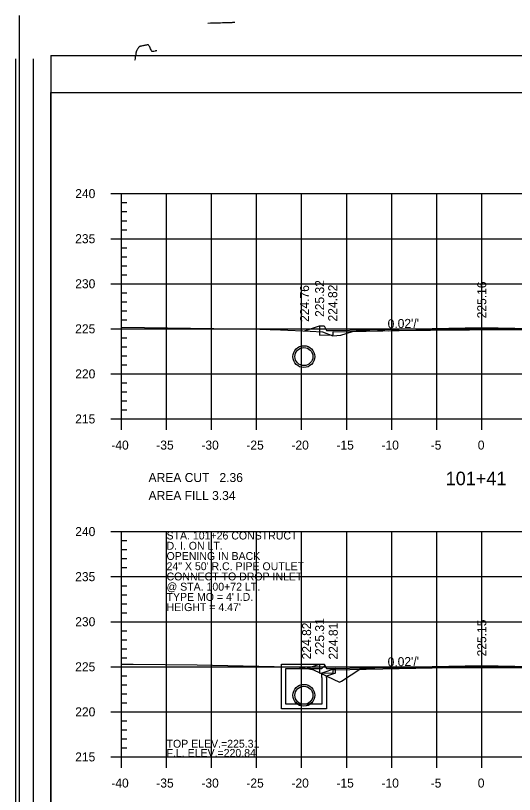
# Model space of a CAD drawing. Extents: x 1367903 to 1373764, y 376865 to 382130.
# Drawn here: x 1369737.8 to 1369848.6, y 377447.5 to 377620.4 of the extents above; entities that cross this region are included whole.
import ezdxf

# ---------------------------------------------------------------- set-up
doc = ezdxf.new("R2010")
doc.units = 0
for name, color, linetype in [('R_Axis', 7, 'Continuous'), ('R_Axis Annot', 7, 'Continuous'), ('R_Border', 7, 'Continuous'), ('R_Border PE', 7, 'Continuous'), ('R_Draft', 7, 'Continuous'), ('R_Exist Surface', 7, 'Continuous'), ('R_Fin Surface', 7, 'Continuous'), ('R_Fin Surface Annot', 7, 'Continuous'), ('R_Grid', 7, 'Continuous'), ('R_Water', 7, 'Continuous'), ('R_Water Annot', 7, 'Continuous')]:
    doc.layers.add(name, color=color, linetype=linetype)

msp = doc.modelspace()

# ---------------------------------------------------------------- linework, layer by layer
for p, q in [((1369796.84, 377476.45), (1369806.34, 377476.45)), ((1369796.84, 377473.45), (1369796.84, 377476.45)), ((1369797.84, 377473.45), (1369797.84, 377475.45)), ((1369797.84, 377475.45), (1369805.84, 377475.45)), ((1369806.5, 377476.12), (1369805.84, 377475.45)), ((1369808.84, 377475.49), (1369805.84, 377474.45)), ((1369806.5, 377476.12), (1369806.34, 377476.45)), ((1369805.84, 377473.45), (1369805.84, 377474.45)), ((1369808.84, 377474.43), (1369806.84, 377473.74)), ((1369806.84, 377473.45), (1369806.84, 377473.74))]:
    msp.add_line(p, q)
for points in [[(1369805.34, 377551.47), (1369805.34, 377550.81), (1369805.34, 377550.81), (1369805.34, 377549.44), (1369808.34, 377549.5), (1369808.34, 377550.17), (1369841.34, 377550.83), (1369874.34, 377550.17), (1369874.34, 377549.5), (1369877.34, 377549.44), (1369877.34, 377550.89), (1369891.34, 377551.17), (1369891.34, 377551.75)], [(1369805.34, 377476.45), (1369805.34, 377475.78), (1369805.34, 377475.78), (1369805.34, 377474.42), (1369808.34, 377474.48), (1369808.34, 377475.14), (1369841.34, 377475.8), (1369874.34, 377475.14), (1369874.34, 377474.48), (1369877.34, 377474.42), (1369877.34, 377475.86), (1369891.34, 377476.14), (1369891.34, 377476.73)], [(1369808.84, 377474.43), (1369808.84, 377475.49)]]:
    msp.add_lwpolyline(points)
at = {"layer": 'R_Axis'}
for p, q in [((1369758.94, 377580.84), (1369763.74, 377580.84)), ((1369761.34, 377530.84), (1369761.34, 377580.84)), ((1369761.34, 377578.84), (1369762.54, 377578.84)), ((1369761.34, 377576.84), (1369762.54, 377576.84)), ((1369761.34, 377574.84), (1369762.54, 377574.84)), ((1369761.34, 377572.84), (1369762.54, 377572.84)), ((1369758.94, 377570.84), (1369763.74, 377570.84)), ((1369761.34, 377568.84), (1369762.54, 377568.84)), ((1369761.34, 377566.84), (1369762.54, 377566.84)), ((1369761.34, 377564.84), (1369762.54, 377564.84)), ((1369761.34, 377562.84), (1369762.54, 377562.84)), ((1369758.94, 377560.84), (1369763.74, 377560.84)), ((1369761.34, 377558.84), (1369762.54, 377558.84)), ((1369761.34, 377556.84), (1369762.54, 377556.84)), ((1369761.34, 377554.84), (1369762.54, 377554.84)), ((1369761.34, 377552.84), (1369762.54, 377552.84)), ((1369758.94, 377550.84), (1369763.74, 377550.84)), ((1369761.34, 377548.84), (1369762.54, 377548.84)), ((1369761.34, 377546.84), (1369762.54, 377546.84)), ((1369761.34, 377544.84), (1369762.54, 377544.84)), ((1369761.34, 377542.84), (1369762.54, 377542.84)), ((1369758.94, 377540.84), (1369763.74, 377540.84)), ((1369761.34, 377538.84), (1369762.54, 377538.84)), ((1369761.34, 377536.84), (1369762.54, 377536.84)), ((1369761.34, 377534.84), (1369762.54, 377534.84)), ((1369761.34, 377528.44), (1369761.34, 377533.24)), ((1369761.34, 377532.84), (1369762.54, 377532.84)), ((1369771.34, 377528.44), (1369771.34, 377533.24)), ((1369781.34, 377528.44), (1369781.34, 377533.24)), ((1369791.34, 377528.44), (1369791.34, 377533.24)), ((1369801.34, 377528.44), (1369801.34, 377533.24)), ((1369811.34, 377528.44), (1369811.34, 377533.24)), ((1369821.34, 377528.44), (1369821.34, 377533.24)), ((1369831.34, 377528.44), (1369831.34, 377533.24)), ((1369841.34, 377528.44), (1369841.34, 377533.24)), ((1369758.94, 377530.84), (1369763.74, 377530.84)), ((1369761.34, 377530.84), (1369921.34, 377530.84)), ((1369758.94, 377505.84), (1369763.74, 377505.84)), ((1369761.34, 377455.84), (1369761.34, 377505.84)), ((1369761.34, 377503.84), (1369762.54, 377503.84)), ((1369761.34, 377501.84), (1369762.54, 377501.84)), ((1369761.34, 377499.84), (1369762.54, 377499.84)), ((1369761.34, 377497.84), (1369762.54, 377497.84)), ((1369758.94, 377495.84), (1369763.74, 377495.84)), ((1369761.34, 377493.84), (1369762.54, 377493.84)), ((1369761.34, 377491.84), (1369762.54, 377491.84)), ((1369761.34, 377489.84), (1369762.54, 377489.84)), ((1369761.34, 377487.84), (1369762.54, 377487.84)), ((1369758.94, 377485.84), (1369763.74, 377485.84)), ((1369761.34, 377483.84), (1369762.54, 377483.84)), ((1369761.34, 377481.84), (1369762.54, 377481.84)), ((1369761.34, 377479.84), (1369762.54, 377479.84)), ((1369761.34, 377477.84), (1369762.54, 377477.84)), ((1369758.94, 377475.84), (1369763.74, 377475.84)), ((1369761.34, 377473.84), (1369762.54, 377473.84)), ((1369761.34, 377471.84), (1369762.54, 377471.84)), ((1369761.34, 377469.84), (1369762.54, 377469.84)), ((1369761.34, 377467.84), (1369762.54, 377467.84)), ((1369758.94, 377465.84), (1369763.74, 377465.84)), ((1369761.34, 377463.84), (1369762.54, 377463.84)), ((1369761.34, 377461.84), (1369762.54, 377461.84)), ((1369761.34, 377459.84), (1369762.54, 377459.84)), ((1369761.34, 377453.44), (1369761.34, 377458.24)), ((1369771.34, 377453.44), (1369771.34, 377458.24)), ((1369781.34, 377453.44), (1369781.34, 377458.24)), ((1369791.34, 377453.44), (1369791.34, 377458.24)), ((1369801.34, 377453.44), (1369801.34, 377458.24)), ((1369811.34, 377453.44), (1369811.34, 377458.24)), ((1369821.34, 377453.44), (1369821.34, 377458.24)), ((1369831.34, 377453.44), (1369831.34, 377458.24)), ((1369841.34, 377453.44), (1369841.34, 377458.24)), ((1369761.34, 377457.84), (1369762.54, 377457.84)), ((1369758.94, 377455.84), (1369763.74, 377455.84)), ((1369761.34, 377455.84), (1369921.34, 377455.84))]:
    msp.add_line(p, q, dxfattribs=at)
at = {"layer": 'R_Border'}
for p, q in [((1369738.61, 377620.35), (1369738.61, 377279.12)), ((1369745.64, 377611.47), (1369949.96, 377611.47)), ((1369745.64, 377611.47), (1369745.64, 377280.59))]:
    msp.add_line(p, q, dxfattribs=at)
at = {"layer": 'R_Border PE'}
for p, q in [((1369737.81, 377610.76), (1369737.81, 377288.8)), ((1369741.72, 377610.76), (1369741.72, 377288.8)), ((1369745.64, 377603.25), (1369949.96, 377603.25)), ((1369745.64, 377288.8), (1369745.64, 377603.25))]:
    msp.add_line(p, q, dxfattribs=at)
for points in [[(1369786.51, 377618.79), (1369786.17, 377618.78), (1369785.97, 377618.78), (1369785.81, 377618.77), (1369785.58, 377618.76), (1369785.42, 377618.76), (1369785.23, 377618.75), (1369784.98, 377618.75), (1369784.79, 377618.74), (1369784.51, 377618.73), (1369784.41, 377618.73), (1369784.36, 377618.73), (1369784.14, 377618.72), (1369784.03, 377618.72), (1369783.81, 377618.71), (1369783.73, 377618.72), (1369783.31, 377618.7), (1369783.06, 377618.7), (1369782.95, 377618.7)], [(1369782.5, 377618.69), (1369782.44, 377618.69), (1369782.17, 377618.68), (1369782.04, 377618.68), (1369781.97, 377618.67), (1369781.81, 377618.67), (1369781.45, 377618.66), (1369781.12, 377618.65), (1369780.49, 377618.63)], [(1369782.95, 377618.7), (1369782.5, 377618.69)], [(1369769.2, 377612.54), (1369769.18, 377612.55), (1369769.16, 377612.55), (1369769.14, 377612.55), (1369769.12, 377612.55), (1369769.09, 377612.55), (1369769.06, 377612.55), (1369769.04, 377612.55), (1369768.9, 377612.51), (1369768.78, 377612.48), (1369768.51, 377612.41), (1369768.29, 377612.36), (1369768.27, 377612.35), (1369768.25, 377612.35), (1369768.22, 377612.34), (1369768.21, 377612.34), (1369768.2, 377612.35), (1369768.18, 377612.35), (1369768.16, 377612.36), (1369768.13, 377612.38), (1369768.11, 377612.39), (1369768.09, 377612.4), (1369768.08, 377612.42), (1369768.06, 377612.45), (1369768.05, 377612.47), (1369768.03, 377612.5), (1369768.01, 377612.55), (1369767.91, 377612.76), (1369767.8, 377613), (1369767.7, 377613.23), (1369767.69, 377613.26), (1369767.68, 377613.28), (1369767.64, 377613.34), (1369767.61, 377613.39), (1369767.49, 377613.57), (1369767.41, 377613.69), (1369767.38, 377613.74), (1369767.36, 377613.76), (1369767.35, 377613.78), (1369767.32, 377613.81), (1369767.31, 377613.83), (1369767.29, 377613.84), (1369767.28, 377613.85), (1369767.25, 377613.87), (1369767.24, 377613.87), (1369767.21, 377613.88), (1369767.18, 377613.88), (1369767.17, 377613.88), (1369767.13, 377613.88), (1369767.02, 377613.86), (1369766.85, 377613.82), (1369766.66, 377613.77), (1369766.51, 377613.74), (1369766.41, 377613.72), (1369766.27, 377613.69), (1369766.15, 377613.66), (1369765.97, 377613.63), (1369765.75, 377613.58), (1369765.7, 377613.57), (1369765.58, 377613.54), (1369765.47, 377613.52), (1369765.43, 377613.51), (1369765.4, 377613.5), (1369765.38, 377613.5), (1369765.36, 377613.49), (1369765.35, 377613.49), (1369765.33, 377613.47), (1369765.31, 377613.46), (1369765.29, 377613.44), (1369765.26, 377613.42), (1369765.23, 377613.39), (1369765.21, 377613.35), (1369765.18, 377613.31), (1369765.14, 377613.26), (1369765.08, 377613.16), (1369764.98, 377613.02), (1369764.9, 377612.89), (1369764.81, 377612.75), (1369764.76, 377612.67), (1369764.72, 377612.62), (1369764.68, 377612.55), (1369764.67, 377612.54), (1369764.66, 377612.52), (1369764.65, 377612.5), (1369764.65, 377612.48), (1369764.64, 377612.46), (1369764.64, 377612.44), (1369764.63, 377612.42), (1369764.62, 377612.39), (1369764.62, 377612.37), (1369764.61, 377612.35), (1369764.61, 377612.33), (1369764.59, 377612.24), (1369764.55, 377612), (1369764.51, 377611.76), (1369764.49, 377611.65), (1369764.4, 377611.18), (1369764.38, 377611.04), (1369764.34, 377610.84), (1369764.28, 377610.54), (1369764.25, 377610.39)]]:
    msp.add_lwpolyline(points, dxfattribs=at)
at = {"layer": 'R_Exist Surface'}
for points in [[(1369761.34, 377551.23), (1369792.07, 377550.79), (1369796.68, 377550.61), (1369803.27, 377550.29), (1369805.98, 377550.19), (1369808.29, 377549.26), (1369810.04, 377549.43), (1369812.66, 377550.21), (1369813.44, 377550.31), (1369817.19, 377550.66), (1369817.37, 377550.66), (1369820.65, 377550.43), (1369821.4, 377550.44), (1369847.22, 377550.71), (1369863.58, 377550.59)], [(1369761.34, 377476.39), (1369763.96, 377476.41), (1369778.11, 377476.28), (1369798.62, 377475.83), (1369800.83, 377475.74), (1369801.65, 377475.62), (1369803.73, 377475.25), (1369803.96, 377475.19), (1369809.72, 377472.4), (1369810.21, 377472.64), (1369814.46, 377475.43), (1369819.16, 377475.65), (1369819.37, 377475.67), (1369820.36, 377475.67), (1369847.59, 377475.7), (1369859.49, 377475.49)]]:
    msp.add_lwpolyline(points, dxfattribs=at)
at = {"layer": 'R_Fin Surface'}
for points in [[(1369801.99, 377550.36), (1369805.34, 377551.47), (1369806.34, 377551.47), (1369806.84, 377550.47), (1369808.34, 377550.5), (1369830.34, 377550.94), (1369841.34, 377551.16), (1369852.34, 377550.94), (1369874.34, 377550.5), (1369875.84, 377550.47), (1369876.34, 377551.47), (1369877.34, 377551.47), (1369881.34, 377551.55), (1369891.34, 377551.75), (1369894.32, 377550.76)], [(1369802.44, 377475.48), (1369805.34, 377476.45), (1369806.34, 377476.45), (1369806.84, 377475.45), (1369808.34, 377475.48), (1369830.34, 377475.92), (1369841.34, 377476.14), (1369852.34, 377475.92), (1369874.34, 377475.48), (1369875.84, 377475.45), (1369876.34, 377476.45), (1369877.34, 377476.45), (1369881.34, 377476.53), (1369891.34, 377476.73), (1369894.61, 377475.64)]]:
    msp.add_lwpolyline(points, dxfattribs=at)
at = {"layer": 'R_Grid'}
for p, q in [((1369761.34, 377580.84), (1369921.34, 377580.84)), ((1369761.34, 377530.84), (1369761.34, 377580.84)), ((1369771.34, 377530.84), (1369771.34, 377580.84)), ((1369781.34, 377530.84), (1369781.34, 377580.84)), ((1369791.34, 377530.84), (1369791.34, 377580.84)), ((1369801.34, 377530.84), (1369801.34, 377580.84)), ((1369811.34, 377530.84), (1369811.34, 377580.84)), ((1369821.34, 377530.84), (1369821.34, 377580.84)), ((1369831.34, 377530.84), (1369831.34, 377580.84)), ((1369841.34, 377530.84), (1369841.34, 377580.84)), ((1369761.34, 377570.84), (1369921.34, 377570.84)), ((1369761.34, 377560.84), (1369921.34, 377560.84)), ((1369761.34, 377550.84), (1369921.34, 377550.84)), ((1369761.34, 377540.84), (1369921.34, 377540.84)), ((1369761.34, 377530.84), (1369921.34, 377530.84)), ((1369761.34, 377505.84), (1369921.34, 377505.84)), ((1369761.34, 377455.84), (1369761.34, 377505.84)), ((1369771.34, 377455.84), (1369771.34, 377505.84)), ((1369781.34, 377455.84), (1369781.34, 377505.84)), ((1369791.34, 377455.84), (1369791.34, 377505.84)), ((1369801.34, 377455.84), (1369801.34, 377505.84)), ((1369811.34, 377455.84), (1369811.34, 377505.84)), ((1369821.34, 377455.84), (1369821.34, 377505.84)), ((1369831.34, 377455.84), (1369831.34, 377505.84)), ((1369841.34, 377455.84), (1369841.34, 377505.84)), ((1369761.34, 377495.84), (1369921.34, 377495.84)), ((1369761.34, 377485.84), (1369921.34, 377485.84)), ((1369761.34, 377475.84), (1369921.34, 377475.84)), ((1369761.34, 377465.84), (1369921.34, 377465.84)), ((1369761.34, 377455.84), (1369921.34, 377455.84))]:
    msp.add_line(p, q, dxfattribs=at)
at = {"layer": 'R_Water'}
for p, q in [((1369801.84, 377547.11), (1369801.84, 377547.06)), ((1369801.84, 377546.69), (1369801.84, 377546.64)), ((1369801.84, 377542.69), (1369801.84, 377542.64)), ((1369801.84, 377542.27), (1369801.84, 377542.23)), ((1369801.8, 377471.93), (1369801.8, 377471.93)), ((1369801.8, 377471.51), (1369801.8, 377471.51)), ((1369801.8, 377467.51), (1369801.8, 377467.51)), ((1369801.8, 377467.1), (1369801.8, 377467.1))]:
    msp.add_line(p, q, dxfattribs=at)
for points in [[(1369806.84, 377473.45), (1369806.84, 377466.51), (1369801.84, 377466.51), (1369796.84, 377466.51), (1369796.84, 377473.45)], [(1369805.84, 377473.45), (1369805.84, 377467.51), (1369801.84, 377467.51), (1369797.84, 377467.51), (1369797.84, 377473.45)]]:
    msp.add_lwpolyline(points, dxfattribs=at)
for centre, radius in [((1369801.84, 377544.67), 2.42), ((1369801.84, 377544.67), 2), ((1369801.84, 377469.52), 2.42), ((1369801.84, 377469.51), 2.42), ((1369801.84, 377469.52), 2), ((1369801.84, 377469.51), 2)]:
    msp.add_circle(centre, radius, dxfattribs=at)

# ---------------------------------------------------------------- texts
at = {"layer": 'R_Axis Annot'}
for s, height, p in [('240', 2, (1369751.06, 377579.84)), ('235', 2, (1369751.05, 377569.84)), ('230', 2, (1369751.06, 377559.84)), ('225', 2, (1369751.05, 377549.84)), ('220', 2, (1369751.06, 377539.84)), ('215', 2, (1369751.05, 377529.84)), ('-40', 2, (1369759.07, 377524.04)), ('-35', 2, (1369769.06, 377524.04)), ('-30', 2, (1369779.07, 377524.04)), ('-25', 2, (1369789.06, 377524.04)), ('-20', 2, (1369799.07, 377524.04)), ('-15', 2, (1369809.06, 377524.04)), ('-10', 2, (1369819.07, 377524.04)), ('-5', 2, (1369830, 377524.04)), ('0', 2, (1369840.46, 377524.04)), ('AREA CUT   2.36', 2, (1369767.34, 377516.84)), ('101+41', 3, (1369833.33, 377516.14)), ('AREA FILL 3.34', 2, (1369767.34, 377512.84)), ('240', 2, (1369751.06, 377504.84)), ('235', 2, (1369751.05, 377494.84)), ('230', 2, (1369751.06, 377484.84)), ('225', 2, (1369751.05, 377474.84)), ('220', 2, (1369751.06, 377464.84)), ('215', 2, (1369751.05, 377454.84)), ('-40', 2, (1369759.07, 377449.04)), ('-35', 2, (1369769.06, 377449.04)), ('-30', 2, (1369779.07, 377449.04)), ('-25', 2, (1369789.06, 377449.04)), ('-20', 2, (1369799.07, 377449.04)), ('-10', 2, (1369819.07, 377449.04)), ('0', 2, (1369840.46, 377449.04)), ('-15', 2, (1369809.06, 377449.04)), ('-5', 2, (1369830, 377449.04))]:
    msp.add_text(s, height=height, dxfattribs=at).set_placement(p)
at = {"layer": 'R_Draft'}
for s, p in [('STA. 101+26 CONSTRUCT', (1369771.34, 377504.09)), ('D. I. ON LT.', (1369771.34, 377501.82)), ('OPENING IN BACK', (1369771.34, 377499.55)), ('24" X 50\' R.C. PIPE OUTLET', (1369771.34, 377497.28)), ('CONNECT TO DROP INLET', (1369771.34, 377495.01)), ('@ STA. 100+72 LT.', (1369771.34, 377492.74)), ("TYPE MO = 4' I.D.", (1369771.34, 377490.47)), ("HEIGHT = 4.47'", (1369771.34, 377488.2))]:
    msp.add_text(s, height=1.75, dxfattribs=at).set_placement(p)
at = {"layer": 'R_Fin Surface Annot'}
for s, rotation, p in [('224.76', 90, (1369802.99, 377552.36)), ('225.32', 90, (1369806.34, 377553.47)), ('224.82', 90, (1369809.24, 377552.47)), ('225.16', 90, (1369842.34, 377553.16)), ("0.02'/'", 1.1458, (1369820.46, 377550.95)), ('225.31', 90, (1369806.34, 377478.45)), ('225.15', 90, (1369842.34, 377478.14)), ('224.82', 90, (1369803.44, 377477.48)), ('224.81', 90, (1369809.36, 377477.45)), ("0.02'/'", 1.1458, (1369820.46, 377475.92))]:
    msp.add_text(s, height=2, rotation=rotation, dxfattribs=at).set_placement(p)
at = {"layer": 'R_Water Annot'}
for s, p in [('TOP ELEV.=225.31', (1369771.34, 377457.89)), ('F.L. ELEV.=220.84', (1369771.34, 377455.84))]:
    msp.add_text(s, height=1.75, dxfattribs=at).set_placement(p)

doc.saveas('drawing.dxf')
